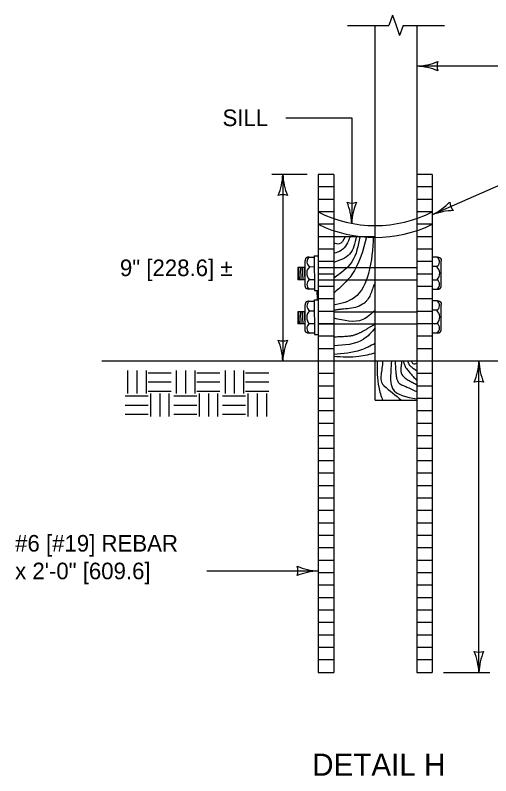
# Model space of a CAD drawing. Extents: x 49991.4 to 50021, y 49987.6 to 50011.4.
# Drawn here: x 50008.027 to 50009.746, y 49991.807 to 49994.556 of the extents above; entities that cross this region are included whole.
import ezdxf

# ---------------------------------------------------------------- set-up
doc = ezdxf.new("R2010")
doc.units = 0
for name, color, linetype in [('Level 1', 7, 'Continuous'), ('Level 2', 7, 'Continuous'), ('Level 3', 7, 'Continuous'), ('Level 4', 7, 'Continuous'), ('Level 6', 7, 'Continuous')]:
    doc.layers.add(name, color=color, linetype=linetype)

msp = doc.modelspace()

# ---------------------------------------------------------------- linework, layer by layer
at = {"layer": 'Level 1'}
for p, q in [((50009.3286, 49993.1642), (50009.3286, 49994.5192)), ((50009.4785, 49994.5192), (50009.4785, 49992.1802)), ((50009.1223, 49993.9802), (50009.1223, 49992.1802)), ((50009.1786, 49993.9802), (50009.1223, 49993.9802)), ((50009.1786, 49993.9802), (50009.1786, 49992.1802)), ((50009.5347, 49993.9802), (50009.4785, 49993.9802)), ((50009.5347, 49993.9802), (50009.5347, 49992.1802)), ((50009.1786, 49993.9352), (50009.1223, 49993.9352)), ((50009.5347, 49993.9352), (50009.4785, 49993.9352)), ((50009.1786, 49993.8902), (50009.1223, 49993.8902)), ((50009.5347, 49993.8902), (50009.4785, 49993.8902)), ((50009.1786, 49993.8452), (50009.1223, 49993.8452)), ((50009.5347, 49993.8452), (50009.4785, 49993.8452)), ((50009.1786, 49993.8002), (50009.1223, 49993.8002)), ((50009.5347, 49993.8002), (50009.4785, 49993.8002)), ((50009.3286, 49993.7552), (50009.1223, 49993.7552)), ((50009.5347, 49993.7552), (50009.4785, 49993.7552)), ((50009.1786, 49993.7102), (50009.1223, 49993.7102)), ((50009.5347, 49993.7102), (50009.4785, 49993.7102)), ((50009.088, 49993.6811), (50009.1081, 49993.681)), ((50009.108, 49993.686), (50009.1083, 49993.5606)), ((50009.108, 49993.686), (50009.1223, 49993.6859)), ((50009.5541, 49993.681), (50009.5347, 49993.681)), ((50009.0755, 49993.5785), (50009.0753, 49993.6681)), ((50009.1786, 49993.6652), (50009.1223, 49993.6652)), ((50009.5347, 49993.6652), (50009.4785, 49993.6652)), ((50009.5671, 49993.5784), (50009.5671, 49993.668)), ((50009.0753, 49993.6435), (50009.0485, 49993.6434)), ((50009.0485, 49993.6434), (50009.0485, 49993.5994)), ((50009.0509, 49993.6434), (50009.053, 49993.5994)), ((50009.0579, 49993.6434), (50009.06, 49993.5994)), ((50009.0649, 49993.6435), (50009.067, 49993.5994)), ((50009.0719, 49993.6435), (50009.074, 49993.5995)), ((50009.0916, 49993.647), (50009.1081, 49993.6469)), ((50009.5508, 49993.647), (50009.5347, 49993.647)), ((50009.0754, 49993.5995), (50009.0485, 49993.5994)), ((50009.1082, 49993.5997), (50009.0906, 49993.5997)), ((50009.1786, 49993.6202), (50009.1223, 49993.6202)), ((50009.5347, 49993.6202), (50009.4785, 49993.6202)), ((50009.5347, 49993.5997), (50009.5519, 49993.5997)), ((50009.1786, 49993.5752), (50009.1223, 49993.5752)), ((50009.5347, 49993.5752), (50009.4785, 49993.5752)), ((50009.1083, 49993.5656), (50009.0883, 49993.5655)), ((50009.1083, 49993.5606), (50009.1223, 49993.561)), ((50009.1192, 49993.5266), (50009.1187, 49993.5609)), ((50009.5347, 49993.5656), (50009.5541, 49993.5656)), ((50009.088, 49993.5217), (50009.108, 49993.5217)), ((50009.108, 49993.5267), (50009.1083, 49993.4013)), ((50009.108, 49993.5267), (50009.1223, 49993.5266)), ((50009.1786, 49993.5302), (50009.1223, 49993.5302)), ((50009.5347, 49993.5302), (50009.4785, 49993.5302)), ((50009.5541, 49993.5232), (50009.5343, 49993.5232)), ((50009.0753, 49993.4842), (50009.0484, 49993.4841)), ((50009.0484, 49993.4841), (50009.0485, 49993.4401)), ((50009.0508, 49993.4841), (50009.0531, 49993.4401)), ((50009.0578, 49993.4841), (50009.0599, 49993.44)), ((50009.0648, 49993.4842), (50009.0671, 49993.44)), ((50009.0718, 49993.4842), (50009.0739, 49993.44)), ((50009.0754, 49993.4192), (50009.0752, 49993.5088)), ((50009.0915, 49993.4876), (50009.1081, 49993.4876)), ((50009.1786, 49993.4852), (50009.1223, 49993.4852)), ((50009.5347, 49993.4852), (50009.4785, 49993.4852)), ((50009.5508, 49993.4891), (50009.5347, 49993.4891)), ((50009.5671, 49993.4206), (50009.5671, 49993.5102)), ((50009.0753, 49993.44), (50009.0485, 49993.4401)), ((50009.1082, 49993.4403), (50009.0905, 49993.4403)), ((50009.1786, 49993.4402), (50009.1223, 49993.4402)), ((50009.5347, 49993.4402), (50009.4785, 49993.4402)), ((50009.5347, 49993.4417), (50009.5519, 49993.4417)), ((50009.1082, 49993.4063), (50009.0882, 49993.4062)), ((50009.1083, 49993.4013), (50009.1222, 49993.4017)), ((50009.5343, 49993.4076), (50009.5541, 49993.4076)), ((50009.1786, 49993.3952), (50009.1223, 49993.3952)), ((50009.5347, 49993.3952), (50009.4785, 49993.3952)), ((50009.1786, 49993.3502), (50009.1223, 49993.3502)), ((50009.5347, 49993.3502), (50009.4785, 49993.3502)), ((50010.4337, 49993.3052), (50008.3401, 49993.3052)), ((50008.4331, 49993.2713), (50008.4331, 49993.1879)), ((50008.4664, 49993.2713), (50008.4664, 49993.1879)), ((50008.4998, 49993.2713), (50008.4998, 49993.1879)), ((50008.5075, 49993.2635), (50008.5909, 49993.2635)), ((50008.6093, 49993.2713), (50008.6093, 49993.1879)), ((50008.6426, 49993.2713), (50008.6426, 49993.1879)), ((50008.676, 49993.2713), (50008.676, 49993.1879)), ((50008.6837, 49993.2635), (50008.7671, 49993.2635)), ((50008.7854, 49993.2713), (50008.7854, 49993.1879)), ((50008.8187, 49993.2713), (50008.8187, 49993.1879)), ((50008.8521, 49993.2713), (50008.8521, 49993.1879)), ((50008.8598, 49993.2635), (50008.9432, 49993.2635)), ((50009.1786, 49993.2602), (50009.1223, 49993.2602)), ((50009.5347, 49993.2602), (50009.4785, 49993.2602)), ((50008.5075, 49993.2302), (50008.5909, 49993.2302)), ((50008.6837, 49993.2302), (50008.7671, 49993.2302)), ((50008.8598, 49993.2302), (50008.9432, 49993.2302)), ((50009.1786, 49993.2152), (50009.1223, 49993.2152)), ((50009.5347, 49993.2152), (50009.4785, 49993.2152)), ((50008.5075, 49993.1968), (50008.5909, 49993.1968)), ((50008.5158, 49993.1885), (50008.5158, 49993.1051)), ((50008.5492, 49993.1885), (50008.5492, 49993.1051)), ((50008.5826, 49993.1885), (50008.5826, 49993.1051)), ((50008.6837, 49993.1968), (50008.7671, 49993.1968)), ((50008.692, 49993.1885), (50008.692, 49993.1051)), ((50008.7254, 49993.1885), (50008.7254, 49993.1051)), ((50008.7588, 49993.1885), (50008.7588, 49993.1051)), ((50008.8598, 49993.1968), (50008.9432, 49993.1968)), ((50008.8681, 49993.1885), (50008.8681, 49993.1051)), ((50008.9015, 49993.1885), (50008.9015, 49993.1051)), ((50008.9349, 49993.1885), (50008.9349, 49993.1051)), ((50008.4241, 49993.1801), (50008.5075, 49993.1801)), ((50008.6003, 49993.1801), (50008.6837, 49993.1801)), ((50008.7764, 49993.1801), (50008.8598, 49993.1801)), ((50009.1786, 49993.1702), (50009.1223, 49993.1702)), ((50009.5347, 49993.1702), (50009.4785, 49993.1702)), ((50008.4241, 49993.1468), (50008.5075, 49993.1468)), ((50008.6003, 49993.1468), (50008.6837, 49993.1468)), ((50008.7764, 49993.1468), (50008.8598, 49993.1468)), ((50008.4241, 49993.1134), (50008.5075, 49993.1134)), ((50008.6003, 49993.1134), (50008.6837, 49993.1134)), ((50008.7764, 49993.1134), (50008.8598, 49993.1134)), ((50009.1786, 49993.1252), (50009.1223, 49993.1252)), ((50009.5347, 49993.1252), (50009.4785, 49993.1252)), ((50009.1786, 49993.0802), (50009.1223, 49993.0802)), ((50009.5347, 49993.0802), (50009.4785, 49993.0802)), ((50009.1786, 49993.0352), (50009.1223, 49993.0352)), ((50009.5347, 49993.0352), (50009.4785, 49993.0352)), ((50009.1786, 49992.9902), (50009.1223, 49992.9902)), ((50009.5347, 49992.9902), (50009.4785, 49992.9902)), ((50009.1786, 49992.9452), (50009.1223, 49992.9452)), ((50009.5347, 49992.9452), (50009.4785, 49992.9452)), ((50009.1786, 49992.9002), (50009.1223, 49992.9002)), ((50009.5347, 49992.9002), (50009.4785, 49992.9002)), ((50009.1786, 49992.8552), (50009.1223, 49992.8552)), ((50009.5347, 49992.8552), (50009.4785, 49992.8552)), ((50009.1786, 49992.8102), (50009.1223, 49992.8102)), ((50009.5347, 49992.8102), (50009.4785, 49992.8102)), ((50009.1786, 49992.7652), (50009.1223, 49992.7652)), ((50009.5347, 49992.7652), (50009.4785, 49992.7652)), ((50009.1786, 49992.7202), (50009.1223, 49992.7202)), ((50009.5347, 49992.7202), (50009.4785, 49992.7202)), ((50009.1786, 49992.6752), (50009.1223, 49992.6752)), ((50009.5347, 49992.6752), (50009.4785, 49992.6752)), ((50009.1786, 49992.6302), (50009.1223, 49992.6302)), ((50009.5347, 49992.6302), (50009.4785, 49992.6302)), ((50009.1786, 49992.5852), (50009.1223, 49992.5852)), ((50009.5347, 49992.5852), (50009.4785, 49992.5852)), ((50009.1786, 49992.5402), (50009.1223, 49992.5402)), ((50009.5347, 49992.5402), (50009.4785, 49992.5402)), ((50009.1786, 49992.4952), (50009.1223, 49992.4952)), ((50009.5347, 49992.4952), (50009.4785, 49992.4952)), ((50009.1786, 49992.4502), (50009.1223, 49992.4502)), ((50009.5347, 49992.4502), (50009.4785, 49992.4502)), ((50009.1786, 49992.4052), (50009.1223, 49992.4052)), ((50009.5347, 49992.4052), (50009.4785, 49992.4052)), ((50009.1786, 49992.3602), (50009.1223, 49992.3602)), ((50009.5347, 49992.3602), (50009.4785, 49992.3602)), ((50009.1786, 49992.3152), (50009.1223, 49992.3152)), ((50009.5347, 49992.3152), (50009.4785, 49992.3152)), ((50009.1786, 49992.2702), (50009.1223, 49992.2702)), ((50009.5347, 49992.2702), (50009.4785, 49992.2702)), ((50009.1786, 49992.2252), (50009.1223, 49992.2252)), ((50009.5347, 49992.2252), (50009.4785, 49992.2252)), ((50009.1223, 49992.1802), (50009.1786, 49992.1802)), ((50009.4785, 49992.1802), (50009.5347, 49992.1802))]:
    msp.add_line(p, q, dxfattribs=at)
msp.add_lwpolyline([(50009.3286, 49993.1642), (50009.4785, 49993.1642)], dxfattribs=at)
for centre, radius, start, end in [((50009.3285, 49994.2479), 0.4524, 242.8849, 297.1151), ((50009.3285, 49994.2239), 0.4712, 244.0506, 295.9494), ((50009.1022, 49993.6645), 0.0205, 125.695, 238.7654), ((50009.5402, 49993.6645), 0.0205, 301.3232, 53.8049), ((50009.1135, 49993.6228), 0.0326, 132.1886, 225.3565), ((50009.529, 49993.6228), 0.0326, 314.7321, 47.9001), ((50009.1013, 49993.5827), 0.0201, 122.182, 238.7624), ((50009.5412, 49993.5826), 0.0201, 301.9244, 57.9066), ((50009.1021, 49993.5052), 0.0205, 126.308, 238.7654), ((50009.5402, 49993.5066), 0.0205, 301.3232, 54.3774), ((50009.1134, 49993.4635), 0.0326, 132.1886, 225.3565), ((50009.529, 49993.4649), 0.0326, 314.7321, 47.9001), ((50009.1012, 49993.4233), 0.0201, 122.182, 238.4917), ((50009.5412, 49993.4247), 0.0201, 301.4901, 57.9066)]:
    msp.add_arc(centre, radius, start, end, dxfattribs=at)
for points in [[(50009.2596, 49993.7552), (50009.2358, 49993.6919), (50009.1786, 49993.6624)], [(50009.2726, 49993.7552), (50009.2443, 49993.6649), (50009.1786, 49993.6053)], [(50009.2377, 49993.7552), (50009.2053, 49993.7056), (50009.1786, 49993.6953)], [(50009.2199, 49993.7552), (50009.1976, 49993.7289), (50009.1786, 49993.733)], [(50009.2965, 49993.7552), (50009.2443, 49993.6184), (50009.1786, 49993.5512)], [(50009.3214, 49993.7552), (50009.304, 49993.6223), (50009.2534, 49993.5351), (50009.1786, 49993.5077)], [(50009.088, 49993.6811), (50009.0874, 49993.6811), (50009.0866, 49993.6809), (50009.086, 49993.6811), (50009.0854, 49993.6809), (50009.0848, 49993.6808), (50009.0842, 49993.6808), (50009.0837, 49993.6806), (50009.0831, 49993.6804), (50009.0825, 49993.6802), (50009.0821, 49993.6801), (50009.0815, 49993.6799), (50009.0809, 49993.6797), (50009.0805, 49993.6793), (50009.0801, 49993.6791), (50009.0795, 49993.6789), (50009.0791, 49993.6784), (50009.0787, 49993.6782), (50009.0783, 49993.6778), (50009.0782, 49993.6774), (50009.0778, 49993.677), (50009.0776, 49993.6766), (50009.077, 49993.6762), (50009.0768, 49993.6758), (50009.0766, 49993.6752), (50009.0764, 49993.6748), (50009.0763, 49993.6741), (50009.0761, 49993.6737), (50009.0759, 49993.6731), (50009.0757, 49993.6725), (50009.0755, 49993.6721), (50009.0754, 49993.6713), (50009.0754, 49993.6707), (50009.0754, 49993.6701), (50009.0752, 49993.6695), (50009.0752, 49993.6687), (50009.0753, 49993.6681)], [(50009.5541, 49993.681), (50009.5549, 49993.681), (50009.5555, 49993.681), (50009.5563, 49993.681), (50009.5569, 49993.681), (50009.5575, 49993.6808), (50009.5581, 49993.6806), (50009.5587, 49993.6806), (50009.5593, 49993.6804), (50009.5599, 49993.6802), (50009.5603, 49993.68), (50009.5609, 49993.6798), (50009.5615, 49993.6796), (50009.5619, 49993.6794), (50009.5623, 49993.679), (50009.5627, 49993.6788), (50009.5631, 49993.6784), (50009.5635, 49993.6782), (50009.5639, 49993.6778), (50009.5643, 49993.6774), (50009.5645, 49993.677), (50009.5649, 49993.6766), (50009.5653, 49993.6762), (50009.5655, 49993.6758), (50009.5657, 49993.6752), (50009.5659, 49993.6748), (50009.5661, 49993.6742), (50009.5663, 49993.6738), (50009.5665, 49993.6732), (50009.5667, 49993.6726), (50009.5667, 49993.672), (50009.5669, 49993.6714), (50009.5671, 49993.6708), (50009.5671, 49993.6702), (50009.5671, 49993.6694), (50009.5671, 49993.6688), (50009.5671, 49993.668)], [(50009.0883, 49993.5655), (50009.0877, 49993.5655), (50009.0869, 49993.5656), (50009.0863, 49993.5656), (50009.0857, 49993.5656), (50009.0851, 49993.5658), (50009.0845, 49993.566), (50009.0839, 49993.5661), (50009.0833, 49993.5661), (50009.0827, 49993.5663), (50009.0821, 49993.5665), (50009.0817, 49993.5667), (50009.0811, 49993.5668), (50009.0806, 49993.5672), (50009.0802, 49993.5674), (50009.0798, 49993.5678), (50009.0794, 49993.5682), (50009.079, 49993.5684), (50009.0786, 49993.5688), (50009.0784, 49993.5692), (50009.078, 49993.5695), (50009.0776, 49993.5699), (50009.0773, 49993.5703), (50009.0771, 49993.5709), (50009.0769, 49993.5713), (50009.0767, 49993.5717), (50009.0763, 49993.5723), (50009.0761, 49993.5729), (50009.076, 49993.5735), (50009.0758, 49993.5741), (50009.0758, 49993.5745), (50009.0756, 49993.5751), (50009.0756, 49993.5759), (50009.0755, 49993.5765), (50009.0755, 49993.5771), (50009.0753, 49993.5777), (50009.0755, 49993.5785)], [(50009.3286, 49993.5884), (50009.3237, 49993.5798), (50009.3199, 49993.57), (50009.3127, 49993.5504), (50009.3035, 49993.5317), (50009.2972, 49993.5232), (50009.2935, 49993.5192), (50009.2915, 49993.5173), (50009.2904, 49993.5164), (50009.2899, 49993.516), (50009.2896, 49993.5157), (50009.2893, 49993.5155), (50009.2636, 49993.5014), (50009.2357, 49993.4954), (50009.207, 49993.4927), (50009.1927, 49993.4911), (50009.1786, 49993.4887)], [(50009.5541, 49993.5656), (50009.5549, 49993.5656), (50009.5555, 49993.5656), (50009.5563, 49993.5656), (50009.5569, 49993.5656), (50009.5575, 49993.5658), (50009.5581, 49993.5658), (50009.5587, 49993.566), (50009.5593, 49993.5662), (50009.5599, 49993.5664), (50009.5603, 49993.5666), (50009.5609, 49993.5668), (50009.5615, 49993.567), (50009.5619, 49993.5672), (50009.5623, 49993.5676), (50009.5627, 49993.5678), (50009.5631, 49993.5682), (50009.5635, 49993.5684), (50009.5639, 49993.5688), (50009.5643, 49993.5692), (50009.5645, 49993.5696), (50009.5649, 49993.57), (50009.5653, 49993.5704), (50009.5655, 49993.5708), (50009.5657, 49993.5714), (50009.5659, 49993.5718), (50009.5661, 49993.5724), (50009.5663, 49993.5728), (50009.5665, 49993.5734), (50009.5667, 49993.574), (50009.5667, 49993.5746), (50009.5669, 49993.5752), (50009.5671, 49993.5758), (50009.5671, 49993.5764), (50009.5671, 49993.5772), (50009.5671, 49993.5778), (50009.5671, 49993.5784)], [(50009.088, 49993.5217), (50009.0874, 49993.5216), (50009.0868, 49993.5216), (50009.086, 49993.5216), (50009.0854, 49993.5216), (50009.0848, 49993.5213), (50009.0842, 49993.5213), (50009.0836, 49993.5213), (50009.083, 49993.5211), (50009.0824, 49993.5209), (50009.082, 49993.5207), (50009.0814, 49993.5204), (50009.0808, 49993.5202), (50009.0804, 49993.52), (50009.08, 49993.5198), (50009.0794, 49993.5196), (50009.0791, 49993.5192), (50009.0787, 49993.5187), (50009.0785, 49993.5183), (50009.0781, 49993.5181), (50009.0777, 49993.5177), (50009.0775, 49993.5173), (50009.0769, 49993.5169), (50009.0767, 49993.5163), (50009.0766, 49993.5159), (50009.0764, 49993.5155), (50009.0762, 49993.5149), (50009.076, 49993.5145), (50009.0758, 49993.5138), (50009.0756, 49993.5132), (50009.0755, 49993.5126), (50009.0753, 49993.512), (50009.0753, 49993.5114), (50009.0753, 49993.5108), (50009.0752, 49993.51), (50009.0752, 49993.5094), (50009.0752, 49993.5088)], [(50009.5541, 49993.5232), (50009.5549, 49993.5232), (50009.5555, 49993.523), (50009.5563, 49993.523), (50009.5569, 49993.523), (50009.5575, 49993.5228), (50009.5581, 49993.5228), (50009.5587, 49993.5226), (50009.5593, 49993.5224), (50009.5599, 49993.5224), (50009.5603, 49993.5222), (50009.5609, 49993.522), (50009.5615, 49993.5218), (50009.5619, 49993.5214), (50009.5623, 49993.5212), (50009.5627, 49993.5208), (50009.5631, 49993.5206), (50009.5635, 49993.5202), (50009.5639, 49993.5198), (50009.5643, 49993.5194), (50009.5645, 49993.5192), (50009.5649, 49993.5188), (50009.5653, 49993.5182), (50009.5655, 49993.5178), (50009.5657, 49993.5174), (50009.5659, 49993.5168), (50009.5661, 49993.5164), (50009.5663, 49993.5158), (50009.5665, 49993.5152), (50009.5667, 49993.5146), (50009.5667, 49993.514), (50009.5669, 49993.5134), (50009.5671, 49993.5128), (50009.5671, 49993.5122), (50009.5671, 49993.5116), (50009.5671, 49993.5108), (50009.5671, 49993.5102)], [(50009.3286, 49993.4896), (50009.2832, 49993.4555), (50009.1786, 49993.4611)], [(50009.3286, 49993.4392), (50009.3199, 49993.4343), (50009.3113, 49993.4292), (50009.3027, 49993.4241), (50009.2941, 49993.4191), (50009.2766, 49993.4095), (50009.2675, 49993.4051), (50009.2628, 49993.4031), (50009.2605, 49993.4021), (50009.2593, 49993.4017), (50009.2587, 49993.4014), (50009.2581, 49993.4012), (50009.2533, 49993.3995), (50009.2485, 49993.3981), (50009.2436, 49993.3969), (50009.2386, 49993.396), (50009.2286, 49993.3946), (50009.2186, 49993.3939), (50009.1984, 49993.3931), (50009.1883, 49993.3925), (50009.1786, 49993.3917)], [(50009.0882, 49993.4062), (50009.0876, 49993.4062), (50009.0868, 49993.4064), (50009.0862, 49993.4063), (50009.0856, 49993.4063), (50009.085, 49993.4065), (50009.0844, 49993.4065), (50009.0838, 49993.4067), (50009.0832, 49993.4068), (50009.0826, 49993.407), (50009.0822, 49993.4072), (50009.0816, 49993.4074), (50009.081, 49993.4076), (50009.0806, 49993.4079), (50009.0802, 49993.4081), (50009.0798, 49993.4083), (50009.0793, 49993.4089), (50009.0789, 49993.4091), (50009.0785, 49993.4095), (50009.0783, 49993.4099), (50009.0779, 49993.4103), (50009.0775, 49993.4106), (50009.0773, 49993.411), (50009.077, 49993.4116), (50009.0768, 49993.412), (50009.0766, 49993.4124), (50009.0764, 49993.413), (50009.076, 49993.4134), (50009.076, 49993.414), (50009.0757, 49993.4146), (50009.0757, 49993.4152), (50009.0755, 49993.4158), (50009.0755, 49993.4164), (50009.0755, 49993.4172), (50009.0754, 49993.4178), (50009.0752, 49993.4184), (50009.0754, 49993.4192)], [(50009.3286, 49993.4253), (50009.2851, 49993.3839), (50009.1786, 49993.3607)], [(50009.5541, 49993.4076), (50009.5549, 49993.4076), (50009.5555, 49993.4076), (50009.5563, 49993.4076), (50009.5569, 49993.4078), (50009.5575, 49993.408), (50009.5581, 49993.408), (50009.5587, 49993.4082), (50009.5593, 49993.4082), (50009.5599, 49993.4084), (50009.5603, 49993.4086), (50009.5609, 49993.4088), (50009.5615, 49993.409), (50009.5619, 49993.4094), (50009.5623, 49993.4096), (50009.5627, 49993.4098), (50009.5631, 49993.4102), (50009.5635, 49993.4104), (50009.5639, 49993.411), (50009.5643, 49993.4112), (50009.5645, 49993.4116), (50009.5649, 49993.412), (50009.5653, 49993.4124), (50009.5655, 49993.413), (50009.5657, 49993.4134), (50009.5659, 49993.4138), (50009.5661, 49993.4144), (50009.5663, 49993.415), (50009.5665, 49993.4156), (50009.5667, 49993.416), (50009.5667, 49993.4166), (50009.5669, 49993.4172), (50009.5671, 49993.418), (50009.5671, 49993.4186), (50009.5671, 49993.4192), (50009.5671, 49993.4198), (50009.5671, 49993.4206)], [(50009.3286, 49993.3694), (50009.2754, 49993.3451), (50009.1786, 49993.3299)], [(50009.3286, 49993.3345), (50009.2695, 49993.3219), (50009.1786, 49993.3219)], [(50009.3358, 49993.3052), (50009.341, 49993.2109), (50009.3551, 49993.1642)], [(50009.3543, 49993.3052), (50009.3545, 49993.3006), (50009.3545, 49993.2978), (50009.3542, 49993.292), (50009.3528, 49993.2802), (50009.3495, 49993.2561), (50009.3501, 49993.234), (50009.3535, 49993.2246), (50009.3564, 49993.2204), (50009.3581, 49993.2185), (50009.3601, 49993.2167), (50009.4231, 49993.1642)], [(50009.3871, 49993.3052), (50009.3849, 49993.2702), (50009.3911, 49993.2067), (50009.4785, 49993.1687)], [(50009.4001, 49993.3052), (50009.4028, 49993.2666), (50009.4033, 49993.2604), (50009.404, 49993.2538), (50009.4066, 49993.2408), (50009.4117, 49993.2295), (50009.4155, 49993.2251), (50009.4178, 49993.2233), (50009.4204, 49993.2219), (50009.4349, 49993.2152), (50009.4494, 49993.2086), (50009.4785, 49993.1954)], [(50009.4236, 49993.3052), (50009.4235, 49993.2987), (50009.4228, 49993.2925), (50009.421, 49993.2801), (50009.421, 49993.2679), (50009.4226, 49993.2619), (50009.424, 49993.2589), (50009.4248, 49993.2575), (50009.4253, 49993.2567), (50009.4256, 49993.2564), (50009.4257, 49993.2562), (50009.4258, 49993.256), (50009.4271, 49993.2541), (50009.4285, 49993.2524), (50009.4314, 49993.2491), (50009.4375, 49993.2435), (50009.4508, 49993.2349), (50009.4648, 49993.2279), (50009.4718, 49993.2242), (50009.4785, 49993.2201)], [(50009.4297, 49993.3052), (50009.4306, 49993.3027), (50009.4311, 49993.3013), (50009.4321, 49993.2983), (50009.4339, 49993.2923), (50009.4361, 49993.2865), (50009.4375, 49993.2838), (50009.4383, 49993.2825), (50009.4387, 49993.2818), (50009.4392, 49993.2812), (50009.4487, 49993.2694), (50009.4586, 49993.258), (50009.4686, 49993.2467), (50009.4736, 49993.241), (50009.4785, 49993.2353)], [(50009.4453, 49993.3052), (50009.4463, 49993.3034), (50009.4465, 49993.3029), (50009.447, 49993.3019), (50009.4479, 49993.2998), (50009.4497, 49993.2956), (50009.4531, 49993.2899), (50009.4539, 49993.2891), (50009.4545, 49993.2886), (50009.4547, 49993.2884), (50009.4576, 49993.2861), (50009.4605, 49993.2838), (50009.4665, 49993.2794), (50009.4725, 49993.2751), (50009.4785, 49993.2708)], [(50009.4589, 49993.3052), (50009.4649, 49993.297), (50009.4785, 49993.298)]]:
    msp.add_spline(points, degree=3, dxfattribs=at)
at = {"layer": 'Level 3'}
for p, q in [((50009.7844, 49994.3716), (50009.4785, 49994.3716)), ((50009.0058, 49994.185), (50009.2436, 49994.185)), ((50009.2436, 49994.185), (50009.2436, 49993.8035)), ((50009.0823, 49993.9802), (50008.9544, 49993.9802)), ((50008.9944, 49993.9802), (50008.9944, 49993.3052)), ((50009.8997, 49993.9946), (50009.5347, 49993.8344)), ((50009.7032, 49992.1802), (50009.7032, 49993.3052)), ((50008.7199, 49992.547), (50009.1223, 49992.547)), ((50009.5747, 49992.1802), (50009.7432, 49992.1802))]:
    msp.add_line(p, q, dxfattribs=at)
for centre, radius, start, end in [((50009.467, 49994.6043), 0.233, 272.8273, 292.0772), ((50009.4693, 49994.1495), 0.2223, 67.456, 87.6395), ((50009.6067, 49994.3716), 0.0548, 162.1388, 197.8612), ((50008.7723, 49993.9894), 0.2223, 337.456, 357.6395), ((50009.2271, 49993.9917), 0.233, 182.8273, 202.0772), ((50008.9944, 49993.852), 0.0548, 72.1388, 107.8612), ((50009.2436, 49993.9317), 0.0548, 252.1388, 287.8612), ((50009.0109, 49993.792), 0.233, 2.8273, 22.0772), ((50009.4657, 49993.7944), 0.2223, 157.456, 177.6395), ((50009.4306, 49994.0429), 0.233, 296.5261, 315.7759), ((50009.6521, 49993.8859), 0.0548, 185.8376, 221.56), ((50009.6156, 49993.6273), 0.2223, 91.1548, 111.3383), ((50008.9944, 49993.4334), 0.0548, 252.1388, 287.8612), ((50008.7617, 49993.2937), 0.233, 2.8273, 22.0772), ((50009.2165, 49993.296), 0.2223, 157.456, 177.6395), ((50009.4811, 49993.3144), 0.2223, 337.456, 357.6395), ((50009.9359, 49993.3167), 0.233, 182.8273, 202.0772), ((50009.7032, 49993.177), 0.0548, 72.1388, 107.8612), ((50009.1315, 49992.7691), 0.2223, 247.456, 267.6395), ((50008.9941, 49992.547), 0.0548, 342.1388, 17.8612), ((50009.1338, 49992.3143), 0.233, 92.8273, 112.0772), ((50009.7032, 49992.3084), 0.0548, 252.1388, 287.8612), ((50009.4705, 49992.1687), 0.233, 2.8273, 22.0772), ((50009.9253, 49992.171), 0.2223, 157.456, 177.6395)]:
    msp.add_arc(centre, radius, start, end, dxfattribs=at)
at = {"layer": 'Level 4'}
for p, q in [((50009.1223, 49993.6434), (50009.4785, 49993.6434)), ((50009.1223, 49993.5998), (50009.4785, 49993.5998)), ((50009.1786, 49993.4842), (50009.4785, 49993.4842)), ((50009.1223, 49993.4404), (50009.4785, 49993.4404))]:
    msp.add_line(p, q, dxfattribs=at)
at = {"layer": 'Level 6'}
for p, q in [((50009.3906, 49994.5558), (50009.3777, 49994.5192)), ((50009.3906, 49994.5558), (50009.4036, 49994.5192)), ((50009.2286, 49994.5192), (50009.3777, 49994.5192)), ((50009.4036, 49994.5192), (50009.4166, 49994.4826)), ((50009.4295, 49994.5192), (50009.4166, 49994.4826)), ((50009.4295, 49994.5192), (50009.5785, 49994.5192))]:
    msp.add_line(p, q, dxfattribs=at)

# ---------------------------------------------------------------- texts
at = {"layer": 'Level 2'}
for s, height, p in [('SILL', 0.06, (50008.7763, 49994.155)), ('9" [228.6] ±', 0.06, (50008.4055, 49993.6127)), ('#6 [#19] REBAR', 0.06, (50008.0265, 49992.617)), ('x 2\'-0" [609.6]', 0.06, (50008.0265, 49992.517)), ('DETAIL H', 0.08, (50009.1005, 49991.8067))]:
    msp.add_text(s, height=height, dxfattribs=at).set_placement(p)

doc.saveas('drawing.dxf')
